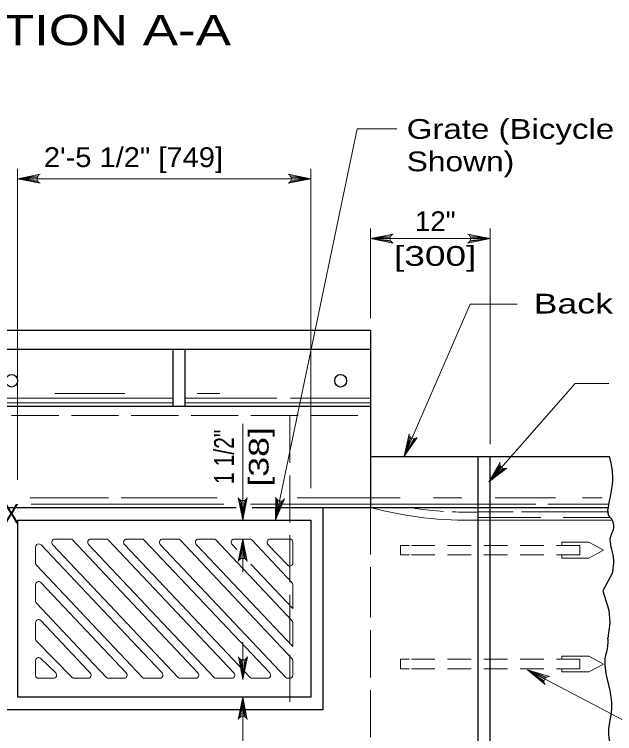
# Model space of a CAD drawing. Extents: x 1352.5 to 1386.5, y 735.9 to 779.9.
# Drawn here: x 1363.03 to 1367.76, y 762.99 to 768.66 of the extents above; entities that cross this region are included whole.
import ezdxf
from ezdxf.enums import TextEntityAlignment as Align

# ---------------------------------------------------------------- set-up
doc = ezdxf.new("R2010")
doc.units = 0
doc.header["$LTSCALE"] = 0.062
doc.linetypes.add('LONG_DASHED', pattern=[7.5, 6, -1.5])
doc.linetypes.add('MEDIUM_DASHED', pattern=[4.5, 3, -1.5])
doc.layers.add('1', color=7, linetype='Continuous', lineweight=13)

msp = doc.modelspace()

# ---------------------------------------------------------------- linework, layer by layer
at = {"layer": '1'}
for p, q in [((1363.05183, 764.99033), (1363.05183, 767.44517)), ((1363.05183, 767.44333), (1363.05183, 767.31658)), ((1365.36467, 764.92325), (1365.36467, 767.44517)), ((1363.21208, 767.38892), (1363.05183, 767.3665)), ((1363.20667, 767.37783), (1363.05183, 767.3665)), ((1365.20442, 767.38892), (1365.36467, 767.3665)), ((1365.20983, 767.37783), (1365.36467, 767.3665)), ((1363.05183, 767.3665), (1364.54392, 767.3665)), ((1363.205, 767.3665), (1363.05183, 767.3665)), ((1363.20783, 767.35217), (1363.05183, 767.3665)), ((1363.214, 767.34175), (1363.05183, 767.3665)), ((1364.54392, 767.3665), (1365.36467, 767.3665)), ((1365.2025, 767.34175), (1365.36467, 767.3665)), ((1365.20867, 767.35217), (1365.36467, 767.3665)), ((1365.2115, 767.3665), (1365.36467, 767.3665)), ((1365.83667, 766.26492), (1365.83667, 766.97317)), ((1366.78067, 765.27092), (1366.78067, 766.97317)), ((1365.99692, 766.91692), (1365.83667, 766.8945)), ((1365.9915, 766.90583), (1365.83667, 766.8945)), ((1365.98983, 766.8945), (1365.83667, 766.8945)), ((1365.99267, 766.88017), (1365.83667, 766.8945)), ((1365.99883, 766.86975), (1365.83667, 766.8945)), ((1365.83667, 766.8945), (1366.78067, 766.8945)), ((1366.6185, 766.86975), (1366.78067, 766.8945)), ((1366.62042, 766.91692), (1366.78067, 766.8945)), ((1366.62467, 766.88017), (1366.78067, 766.8945)), ((1366.62583, 766.90583), (1366.78067, 766.8945)), ((1366.6275, 766.8945), (1366.78067, 766.8945)), ((1363.34525, 765.672), (1363.89883, 765.672)), ((1364.46767, 765.672), (1364.64708, 765.672)), ((1362.68408, 765.63458), (1364.27908, 765.63458)), ((1364.3735, 765.63458), (1365.09808, 765.63458)), ((1365.20567, 765.63458), (1365.83667, 765.63458)), ((1361.73025, 765.59708), (1364.27908, 765.59708)), ((1364.3735, 765.59708), (1365.83667, 765.59708)), ((1364.828, 764.67258), (1364.828, 765.43117)), ((1366.14567, 765.33275), (1366.10292, 765.17667)), ((1366.15367, 765.32333), (1366.10292, 765.17667)), ((1366.16342, 765.31742), (1366.10292, 765.17667)), ((1366.18975, 765.31583), (1366.10292, 765.17667)), ((1366.17775, 765.31425), (1366.10292, 765.17667)), ((1366.85842, 765.10842), (1366.76983, 764.973)), ((1366.86325, 765.097), (1366.76983, 764.973)), ((1366.87067, 765.08833), (1366.76983, 764.973)), ((1366.88333, 765.08092), (1366.76983, 764.973)), ((1366.89517, 765.07875), (1366.76983, 764.973)), ((1363.15192, 764.8475), (1363.76783, 764.8475)), ((1363.86875, 764.8475), (1364.62492, 764.8475)), ((1364.80558, 764.83283), (1364.828, 764.67258)), ((1364.81667, 764.82742), (1364.828, 764.67258)), ((1364.85275, 764.83475), (1364.828, 764.67258)), ((1364.84242, 764.82858), (1364.828, 764.67258)), ((1364.828, 764.82575), (1364.828, 764.67258)), ((1365.09592, 764.83742), (1365.087, 764.67258)), ((1365.10492, 764.82925), (1365.087, 764.67258)), ((1365.14208, 764.82583), (1365.087, 764.67258)), ((1365.1185, 764.8235), (1365.087, 764.67258)), ((1365.13, 764.82275), (1365.087, 764.67258)), ((1365.25642, 764.8475), (1366.06967, 764.8475)), ((1366.33383, 764.8475), (1366.5565, 764.8475)), ((1366.82067, 764.8475), (1367.297, 764.8475)), ((1367.50775, 764.8475), (1367.66508, 764.8475)), ((1363.15783, 764.7975), (1364.67942, 764.7975)), ((1364.88983, 764.7975), (1367.13975, 764.7975)), ((1365.11742, 764.81808), (1365.08742, 764.67475)), ((1367.23475, 764.7975), (1367.716, 764.7975)), ((1366.68625, 764.73608), (1366.96083, 764.73608)), ((1367.02858, 764.73608), (1367.71692, 764.73608)), ((1366.68625, 764.69175), (1367.18008, 764.69175)), ((1366.68625, 764.67258), (1367.74133, 764.67258)), ((1367.35742, 764.69175), (1367.7295, 764.69175)), ((1364.31933, 763.43067), (1363.32817, 764.48008)), ((1363.34483, 764.52267), (1363.46692, 764.52267)), ((1364.47483, 763.466), (1363.48358, 764.51533)), ((1364.60258, 763.43067), (1363.61133, 764.48008)), ((1363.62808, 764.52267), (1363.75008, 764.52267)), ((1364.758, 763.466), (1363.76683, 764.51533)), ((1364.88575, 763.43067), (1363.89508, 764.47958)), ((1363.91367, 764.52267), (1364.03208, 764.52267)), ((1365.04117, 763.466), (1364.05067, 764.51467)), ((1365.16892, 763.43067), (1364.17775, 764.48008)), ((1364.19442, 764.52267), (1364.3165, 764.52267)), ((1365.21617, 763.58058), (1364.33317, 764.51533)), ((1364.516, 764.42175), (1364.46092, 764.48008)), ((1364.47767, 764.52267), (1364.59975, 764.52267)), ((1365.21617, 763.88042), (1364.61642, 764.51533)), ((1364.78192, 764.44008), (1364.74417, 764.48008)), ((1364.76083, 764.52267), (1364.88292, 764.52267)), ((1364.80325, 764.36058), (1364.828, 764.52267)), ((1364.81358, 764.36667), (1364.828, 764.52267)), ((1364.828, 764.3695), (1364.828, 764.52267)), ((1364.83933, 764.36792), (1364.828, 764.52267)), ((1364.85042, 764.36242), (1364.828, 764.52267)), ((1364.828, 764.26017), (1364.828, 764.52267)), ((1365.21617, 764.18025), (1364.89958, 764.51533)), ((1365.18283, 764.3155), (1365.02733, 764.48008)), ((1365.1995, 764.52267), (1365.044, 764.52267)), ((1365.22308, 764.33317), (1365.22308, 764.49767)), ((1367.34708, 764.47275), (1367.34708, 764.49767)), ((1367.5595, 764.49767), (1367.46967, 764.49767)), ((1367.5595, 764.49767), (1367.63158, 764.4585)), ((1363.1935, 764.333), (1363.1935, 764.45842)), ((1364.04242, 763.62392), (1363.23767, 764.47592)), ((1366.07267, 764.47275), (1366.07267, 764.39775)), ((1366.14392, 764.47275), (1366.07267, 764.47275)), ((1367.48867, 764.39775), (1367.48867, 764.47275)), ((1367.5595, 764.37275), (1367.67442, 764.43525)), ((1365.22308, 763.67317), (1364.51967, 764.41783)), ((1366.14392, 764.39775), (1366.07267, 764.39775)), ((1367.34708, 764.39775), (1367.34708, 764.37275)), ((1367.5595, 764.37275), (1367.47592, 764.37275)), ((1363.94683, 763.52517), (1363.20042, 764.31542)), ((1365.22308, 763.97308), (1364.89058, 764.32508)), ((1363.1935, 764.1625), (1363.1935, 764.03333)), ((1363.90842, 763.466), (1363.23375, 764.18025)), ((1365.22308, 763.97308), (1365.22308, 764.16258)), ((1363.65383, 763.53558), (1363.20042, 764.01567)), ((1363.1935, 763.7335), (1363.1935, 763.86275)), ((1363.60867, 763.48342), (1363.23375, 763.88042)), ((1365.22308, 763.67317), (1365.22308, 763.86275)), ((1363.48108, 763.43067), (1363.20042, 763.71583)), ((1364.828, 763.41508), (1364.828, 763.70742)), ((1363.35292, 763.466), (1363.23375, 763.58058)), ((1364.19158, 763.466), (1364.04242, 763.62392)), ((1364.80683, 763.57533), (1364.82925, 763.41508)), ((1364.85408, 763.57717), (1364.82925, 763.41508)), ((1364.84367, 763.57108), (1364.82925, 763.41508)), ((1366.07267, 763.57325), (1366.07267, 763.49825)), ((1366.14392, 763.57325), (1366.07267, 763.57325)), ((1367.34708, 763.57325), (1367.34708, 763.59825)), ((1367.5595, 763.59825), (1367.46967, 763.59825)), ((1367.48867, 763.49825), (1367.48867, 763.57325)), ((1367.5595, 763.59825), (1367.60967, 763.57092)), ((1363.1935, 763.56292), (1363.1935, 763.44833)), ((1363.75292, 763.43067), (1363.65383, 763.53558)), ((1364.03617, 763.43067), (1363.94683, 763.52517)), ((1364.81792, 763.56992), (1364.82925, 763.41508)), ((1364.82925, 763.56825), (1364.82925, 763.41508)), ((1365.22308, 763.44833), (1365.22308, 763.56292)), ((1363.62517, 763.466), (1363.60867, 763.48342)), ((1366.14392, 763.49825), (1366.07267, 763.49825)), ((1367.20933, 763.417), (1367.07508, 763.49067)), ((1367.205, 763.403), (1367.07508, 763.49067)), ((1367.20533, 763.391), (1367.07508, 763.49067)), ((1367.21633, 763.42617), (1367.07508, 763.49067)), ((1367.22642, 763.43333), (1367.07508, 763.49067)), ((1367.34708, 763.49825), (1367.34708, 763.47333)), ((1367.5595, 763.47333), (1367.46967, 763.47333)), ((1367.5595, 763.47333), (1367.625, 763.50892)), ((1363.22542, 763.42333), (1363.21708, 763.42333)), ((1363.22542, 763.42333), (1363.33625, 763.42333)), ((1363.49775, 763.42333), (1363.6085, 763.42333)), ((1363.76967, 763.42333), (1363.89175, 763.42333)), ((1364.05283, 763.42333), (1364.17492, 763.42333)), ((1364.336, 763.42333), (1364.45808, 763.42333)), ((1364.61925, 763.42333), (1364.74133, 763.42333)), ((1364.90242, 763.42333), (1365.0245, 763.42333)), ((1365.18567, 763.42333), (1365.1995, 763.42333)), ((1364.80325, 763.11333), (1364.828, 763.27542)), ((1364.81358, 763.11942), (1364.828, 763.27542)), ((1364.828, 763.12225), (1364.828, 763.27542)), ((1364.83933, 763.12067), (1364.828, 763.27542)), ((1364.85042, 763.11517), (1364.828, 763.27542)), ((1364.828, 762.45833), (1364.828, 763.27342))]:
    msp.add_line(p, q, dxfattribs=at)
at = {"layer": '1', "lineweight": 25}
for p, q in [((1360.17267, 766.17175), (1365.83667, 766.17175)), ((1365.83667, 766.17175), (1365.83667, 764.77258)), ((1360.17267, 766.02183), (1365.83667, 766.02183)), ((1364.27908, 765.57208), (1364.27908, 766.02183)), ((1364.3735, 765.57208), (1364.3735, 766.02183)), ((1360.17267, 765.57208), (1365.83667, 765.57208)), ((1367.72292, 765.17233), (1365.83667, 765.17233)), ((1366.68625, 764.252), (1366.68625, 765.17233)), ((1366.78067, 764.26117), (1366.78067, 765.17233)), ((1358.29033, 764.77258), (1364.77742, 764.77258)), ((1364.90267, 764.77258), (1367.716, 764.77258)), ((1366.68625, 763.03533), (1366.68625, 764.252)), ((1366.78067, 761.67433), (1366.78067, 764.26117)), ((1366.68625, 761.67433), (1366.68625, 763.03533))]:
    msp.add_line(p, q, dxfattribs=at)
at = {"layer": '1', "linetype": 'LONG_DASHED'}
for p, q in [((1360.17267, 765.49717), (1365.83667, 765.49717)), ((1365.1995, 765.49717), (1365.1995, 763.1735))]:
    msp.add_line(p, q, dxfattribs=at)
at = {"layer": '1', "linetype": 'MEDIUM_DASHED'}
for p, q in [((1367.34708, 764.49767), (1367.5595, 764.49767)), ((1367.67442, 764.43525), (1367.5595, 764.49767)), ((1367.48867, 764.47275), (1366.07267, 764.47275)), ((1367.67442, 764.43525), (1367.5595, 764.37275)), ((1367.48867, 764.39775), (1366.07267, 764.39775)), ((1367.34708, 764.37275), (1367.5595, 764.37275)), ((1367.48867, 763.57325), (1366.07267, 763.57325)), ((1367.34708, 763.59825), (1367.5595, 763.59825)), ((1367.67442, 763.53575), (1367.5595, 763.59825)), ((1367.67442, 763.53575), (1367.5595, 763.47333)), ((1367.48867, 763.49825), (1366.07267, 763.49825)), ((1367.34708, 763.47333), (1367.5595, 763.47333))]:
    msp.add_line(p, q, dxfattribs=at)
at = {"layer": '1'}
for points in [[(1366.04358, 767.75917), (1365.73158, 767.75917), (1365.087, 764.67258)], [(1363.22883, 767.33108), (1363.05183, 767.3665), (1363.22883, 767.40192)], [(1365.18767, 767.33108), (1365.36467, 767.3665), (1365.18767, 767.40192)], [(1366.01367, 766.85908), (1365.83667, 766.8945), (1366.01367, 766.92992)], [(1366.60367, 766.85908), (1366.78067, 766.8945), (1366.60367, 766.92992)], [(1366.10292, 765.17667), (1366.6225, 766.37658), (1366.99467, 766.37658)], [(1366.76983, 764.973), (1367.45217, 765.75117), (1367.71583, 765.75117)], [(1366.20542, 765.32525), (1366.10292, 765.17667), (1366.14033, 765.35325)], [(1366.913, 765.08292), (1366.76983, 764.973), (1366.85967, 765.12958)], [(1364.86342, 764.84958), (1364.828, 764.67258), (1364.79258, 764.84958)], [(1365.0885, 764.85425), (1365.087, 764.67258), (1365.15825, 764.83967)], [(1364.79258, 764.34567), (1364.828, 764.52267), (1364.86342, 764.34567)], [(1364.86467, 763.59208), (1364.82925, 763.41508), (1364.79392, 763.59208)], [(1367.07508, 763.49067), (1367.99117, 763.00975), (1368.16958, 763.00975)], [(1367.21325, 763.3745), (1367.07508, 763.49067), (1367.24733, 763.43667)], [(1364.79258, 763.09842), (1364.828, 763.27542), (1364.86342, 763.09842)]]:
    msp.add_lwpolyline(points, dxfattribs=at)
at = {"layer": '1', "lineweight": 25}
for points in [[(1365.45908, 764.77258), (1365.45908, 764.33933), (1365.45908, 763.1735)], [(1363.05183, 764.67258), (1363.05183, 763.82242), (1363.05183, 763.27342)], [(1363.05183, 764.67258), (1364.45067, 764.67258), (1365.36467, 764.67258)], [(1365.36467, 764.67258), (1365.36467, 764.33933), (1365.36467, 763.27342)], [(1367.74675, 764.257), (1367.66933, 764.11483), (1367.71583, 763.96217), (1367.72358, 763.86033), (1367.70975, 763.74067)], [(1365.36467, 763.27342), (1363.49225, 763.27342), (1363.05183, 763.27342)], [(1365.45908, 763.1735), (1363.63192, 763.1735), (1360.55025, 763.1735)]]:
    msp.add_lwpolyline(points, dxfattribs=at)
at = {"layer": '1', "linetype": 'LONG_DASHED'}
msp.add_lwpolyline([(1365.83667, 764.77258), (1365.83667, 764.27483), (1365.83667, 762.67375)], dxfattribs=at)
at = {"layer": '1'}
for centre, radius, start, end in [((1363.24317, 767.36656), 0.0382, 112.08782, 247.91395), ((1365.17338, 767.36656), 0.0382, 292.08605, 67.91218), ((1366.02797, 766.89456), 0.0382, 112.08782, 247.91395), ((1366.58938, 766.89456), 0.0382, 292.08605, 67.91218), ((1366.17848, 765.35239), 0.0382, 178.80874, 314.63487), ((1366.89571, 765.11703), 0.0382, 160.9266, 296.75272), ((1364.82797, 764.8639), 0.0382, 202.08782, 337.91395), ((1365.12639, 764.86102), 0.03845, 190.29027, 326.1164), ((1363.21904, 764.45839), 0.02557, 43.36645, 180), ((1363.91369, 764.49712), 0.02557, 90, 223.3613), ((1364.03206, 764.49712), 0.02557, 43.36996, 90), ((1364.82805, 764.3314), 0.0382, 22.08782, 157.91395), ((1363.21904, 764.33297), 0.02557, 180, 223.36866), ((1364.82924, 763.60637), 0.0382, 202.08782, 337.91395), ((1367.24286, 763.39874), 0.0382, 83.342, 219.16813), ((1364.82805, 763.08415), 0.0382, 22.08782, 157.91395)]:
    msp.add_arc(centre, radius, start, end, dxfattribs=at)
at = {"layer": '1', "lineweight": 25}
for centre in [(1363.00467, 765.77197), (1365.60067, 765.77197)]:
    msp.add_ellipse(centre, major_axis=(0, 0.04997), ratio=0.944544, dxfattribs=at)
at = {"layer": '1'}
for centre, major_axis, start_param, end_param in [((1366.59632, 767.91314), (0, -3.24194), 6.0324912, 6.312565), ((1366.59632, 767.91314), (0, -3.17847), 6.1465046, 6.2221804), ((1366.59632, 767.91314), (0, -3.17847), 6.2446843, 6.312565), ((1363.34485, 764.4977), (0, -0.02499), 3.1415927, 5.4977871), ((1363.4669, 764.4977), (0, 0.02499), 5.4977871, 6.2831853), ((1363.62805, 764.4977), (0, -0.02499), 3.1415927, 5.4977871), ((1363.7501, 764.4977), (0, 0.02499), 5.4977871, 6.2831853), ((1364.19445, 764.4977), (0, -0.02499), 3.1415927, 5.4977871), ((1364.3165, 764.4977), (0, 0.02499), 5.4977871, 6.2831853), ((1364.47765, 764.4977), (0, -0.02499), 3.1415927, 5.4977871), ((1364.59974, 764.4977), (0, 0.02499), 5.4977871, 6.2831853), ((1364.76081, 764.4977), (0, -0.02499), 3.1415927, 5.4977871), ((1364.8829, 764.4977), (0, 0.02499), 5.4977871, 6.2831853), ((1365.04405, 764.4977), (0, -0.02499), 3.1415927, 5.4977871), ((1365.19947, 764.4977), (0, 0.02499), 4.712389, 6.2831853), ((1365.19947, 764.33315), (0, -0.02499), 5.4977871, 7.8539816), ((1363.21707, 764.16254), (0, 0.02499), 5.4977871, 7.8539816), ((1365.19947, 764.16254), (0, 0.02499), 4.712389, 5.4977871), ((1363.21707, 764.03333), (0, 0.02499), 1.5707963, 2.3561945), ((1363.21707, 763.86271), (0, 0.02499), 5.4977871, 7.8539816), ((1365.19947, 763.86271), (0, 0.02499), 4.712389, 5.4977871), ((1363.21707, 763.7335), (0, 0.02499), 1.5707963, 2.3561945), ((1363.21707, 763.56289), (0, 0.02499), 5.4977871, 7.8539816), ((1365.19947, 763.56289), (0, 0.02499), 4.712389, 5.4977871), ((1363.33622, 763.44831), (0, -0.02499), 6.2831853, 8.6393798), ((1363.6085, 763.44831), (0, -0.02499), 6.2831853, 8.6393798), ((1363.8917, 763.44831), (0, -0.02499), 6.2831853, 8.6393798), ((1364.1749, 763.44831), (0, -0.02499), 6.2831853, 8.6393798), ((1364.4581, 763.44831), (0, -0.02499), 6.2831853, 8.6393798), ((1364.7413, 763.44831), (0, -0.02499), 6.2831853, 8.6393798), ((1365.0245, 763.44831), (0, -0.02499), 6.2831853, 8.6393798), ((1363.21707, 763.44831), (0, 0.02499), 1.5707963, 3.1415927), ((1363.49774, 763.44831), (0, -0.02499), 5.4977871, 6.2831853), ((1363.76965, 763.44831), (0, -0.02499), 5.4977871, 6.2831853), ((1364.05285, 763.44831), (0, -0.02499), 5.4977871, 6.2831853), ((1364.33605, 763.44831), (0, -0.02499), 5.4977871, 6.2831853), ((1364.61925, 763.44831), (0, -0.02499), 5.4977871, 6.2831853), ((1364.90245, 763.44831), (0, -0.02499), 5.4977871, 6.2831853), ((1365.18565, 763.44831), (0, -0.02499), 5.4977871, 6.2831853), ((1365.19947, 763.44831), (0, 0.02499), 3.1415927, 4.712389)]:
    msp.add_ellipse(centre, major_axis=major_axis, ratio=0.944544, start_param=start_param, end_param=end_param, dxfattribs=at)
at = {"layer": '1', "lineweight": 25}
for points in [[(1358.28467, 765.17233), (1358.27392, 765.12667), (1358.2975, 765.03625), (1358.28183, 764.97875), (1358.263, 764.8895), (1358.2955, 764.75042), (1358.29975, 764.70767), (1358.27567, 764.65417), (1358.30367, 764.527), (1358.276, 764.413), (1358.29917, 764.27292), (1358.27708, 764.15292), (1358.308, 764.03467), (1358.2615, 763.91375), (1358.30475, 763.80333), (1358.30933, 763.79042), (1358.28633, 763.67242), (1358.307, 763.56908), (1358.30733, 763.5055), (1358.26458, 763.39358), (1358.2765, 763.35383), (1358.31542, 763.28217), (1358.33125, 763.166), (1358.2845, 763.03125), (1358.26858, 762.95183), (1358.2935, 762.80483), (1358.2925, 762.70558), (1358.27417, 762.57167), (1358.29075, 762.43958), (1358.27958, 762.36417), (1358.30842, 762.236), (1358.29917, 762.16067), (1358.29425, 762.13983), (1358.30233, 762.00375), (1358.26642, 761.91058), (1358.28425, 761.722), (1358.26283, 761.65158), (1358.28, 761.586), (1358.3085, 761.50242), (1358.29175, 761.34075), (1358.2805, 761.25842), (1358.29475, 761.17592), (1358.35658, 761.13), (1358.51342, 761.13717), (1358.55292, 761.12108), (1358.56608, 761.11508), (1358.63575, 761.09783), (1358.76925, 761.133), (1358.85692, 761.11367), (1358.89675, 761.13533), (1358.97408, 761.129), (1359.03258, 761.11875), (1359.12533, 761.14317), (1359.181, 761.13592), (1359.29192, 761.09167), (1359.431, 761.11583), (1359.51567, 761.08167), (1359.62733, 761.11192), (1359.73958, 761.09942), (1359.86158, 761.11775), (1359.87758, 761.11667), (1359.968, 761.08742), (1360.04842, 761.10192), (1360.08075, 761.12558), (1360.16192, 761.12125), (1360.21442, 761.09217), (1360.28625, 761.09775), (1360.36108, 761.11825), (1360.50533, 761.09767), (1360.6295, 761.13883), (1360.74825, 761.12333), (1360.84658, 761.13875), (1360.96342, 761.10742), (1361.01933, 761.13), (1361.08833, 761.13558), (1361.15683, 761.0975), (1361.255, 761.08808), (1361.27867, 761.09392), (1361.43375, 761.122), (1361.49517, 761.11967), (1361.53275, 761.10167), (1361.57025, 761.08258), (1361.784, 761.11633), (1361.85842, 761.09508), (1362.07767, 761.11092), (1362.13883, 761.09375), (1362.31467, 761.11475), (1362.37792, 761.11242), (1362.4625, 761.07225), (1362.54092, 761.07883), (1362.56267, 761.08175), (1362.68658, 761.099), (1362.80325, 761.06467), (1363.02833, 761.09833), (1363.14808, 761.08083), (1363.22175, 761.07458), (1363.42808, 761.12617)], [(1367.74675, 764.257), (1367.75108, 764.2895), (1367.75392, 764.37875), (1367.731, 764.53767), (1367.73875, 764.5615), (1367.75533, 764.61108), (1367.74, 764.67858), (1367.71758, 764.7065), (1367.71567, 764.78892), (1367.74658, 765.04692), (1367.72292, 765.17233)], [(1363.42808, 761.12617), (1363.5015, 761.11192), (1363.58433, 761.08667), (1363.71025, 761.11292), (1363.82258, 761.10842), (1363.96392, 761.08083), (1364.08033, 761.11008), (1364.13517, 761.11383), (1364.25383, 761.08742), (1364.36542, 761.10275), (1364.38058, 761.10467), (1364.42317, 761.11442), (1364.52667, 761.07417), (1364.59075, 761.06992), (1364.7535, 761.10483), (1364.913, 761.08817), (1364.96483, 761.08), (1365.12567, 761.11792), (1365.19458, 761.11558), (1365.34058, 761.07717), (1365.49958, 761.11117), (1365.56283, 761.11083), (1365.62867, 761.08567), (1365.85458, 761.11733), (1365.87358, 761.12125), (1366.00542, 761.08483), (1366.0735, 761.09242), (1366.13517, 761.12592), (1366.1975, 761.12758), (1366.28025, 761.09342), (1366.40317, 761.10675), (1366.54583, 761.11992), (1366.70225, 761.08842), (1366.90017, 761.14008), (1367.04608, 761.10167), (1367.23808, 761.1315), (1367.32383, 761.11317), (1367.40117, 761.10983), (1367.48458, 761.13625), (1367.55625, 761.126), (1367.5685, 761.12592), (1367.6195, 761.12367), (1367.71983, 761.153), (1367.74517, 761.22825), (1367.70875, 761.45275), (1367.73417, 761.53308), (1367.72342, 761.68), (1367.73617, 761.72667), (1367.74733, 761.803), (1367.7125, 761.90333), (1367.71708, 761.98183), (1367.7465, 762.08583), (1367.71558, 762.20308), (1367.74217, 762.31125), (1367.72192, 762.45425), (1367.71925, 762.47008), (1367.70883, 762.5615), (1367.73958, 762.71125), (1367.73667, 762.882), (1367.7185, 762.95358), (1367.73758, 763.158), (1367.73775, 763.25817), (1367.71267, 763.39033), (1367.689, 763.57608), (1367.71, 763.68717), (1367.70975, 763.74067)]]:
    msp.add_spline(points, degree=3, dxfattribs=at)

# ---------------------------------------------------------------- texts
at = {"layer": '1'}
for s, height, width, p in [('SECTION A-A', 0.24, 1.3, (1362.06925, 768.42)), ('Grate (Bicycle Safe', 0.156, 1.25, (1366.12158, 767.68117)), ('2\'-5 1/2" [749]', 0.156, 1.1, (1363.25867, 767.4585)), ('Shown)', 0.156, 1.2, (1366.12158, 767.42517)), ('Back of curb', 0.156, 1.35, (1367.12317, 766.30267))]:
    msp.add_text(s, height=height, dxfattribs=dict(at, width=width)).set_placement(p)
for s, width, p in [('12"', 1.05, (1366.34667, 766.953)), ('[300]', 1.4, (1366.34667, 766.679)), ('X', 0.9, (1363.00192, 764.64367))]:
    msp.add_text(s, height=0.156, dxfattribs=dict(at, width=width)).set_placement(p, align=Align.CENTER)
for s, width, p in [('1 1/2"', 0.8, (1364.758, 765.17104)), ('[38]', 1.35, (1365.032, 765.171))]:
    msp.add_text(s, height=0.156, rotation=90, dxfattribs=dict(at, width=width)).set_placement(p, align=Align.CENTER)

doc.saveas('drawing.dxf')
